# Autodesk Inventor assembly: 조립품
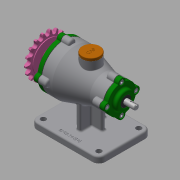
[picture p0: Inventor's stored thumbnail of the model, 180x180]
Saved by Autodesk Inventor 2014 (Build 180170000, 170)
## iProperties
Created: 2020-12
Part Number: 조립품
Document SubType Name: Assembly
Designer: kh
Author: kh
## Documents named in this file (15)
- C:\Users\kh\Desktop\701206V1028\조립품.iam
- C:\Users\kh\Desktop\701206V1028\본체.ipt
- C:\Users\kh\Desktop\701206V1028\앞커버.ipt
- C:\Users\kh\Desktop\701206V1028\베어링 6203.ipt
- C:\Users\kh\Desktop\701206V1028\오일 실 17 30 8.ipt
- C:\Users\kh\Desktop\701206V1028\뒤커버.ipt
- C:\Users\kh\Desktop\701206V1028\베어링 6200.ipt
- C:\Users\kh\Desktop\701206V1028\오일 실 10 20 7.ipt
- C:\Users\kh\Desktop\701206V1028\축.ipt
- C:\Users\kh\Desktop\701206V1028\개스킷 A.ipt
- C:\Users\kh\Desktop\701206V1028\개스킷 B.ipt
- C:\Users\kh\Desktop\701206V1028\키 4x4x14.ipt
- C:\Users\kh\Desktop\701206V1028\마개.ipt
- C:\Users\kh\Desktop\701206V1028\스프로킷.ipt
- C:\Users\kh\Desktop\701206V1028\볼트 M5.ipt
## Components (2 placed, 2 different names)
1. 개스킷 A:1
2. 개스킷 B:1
